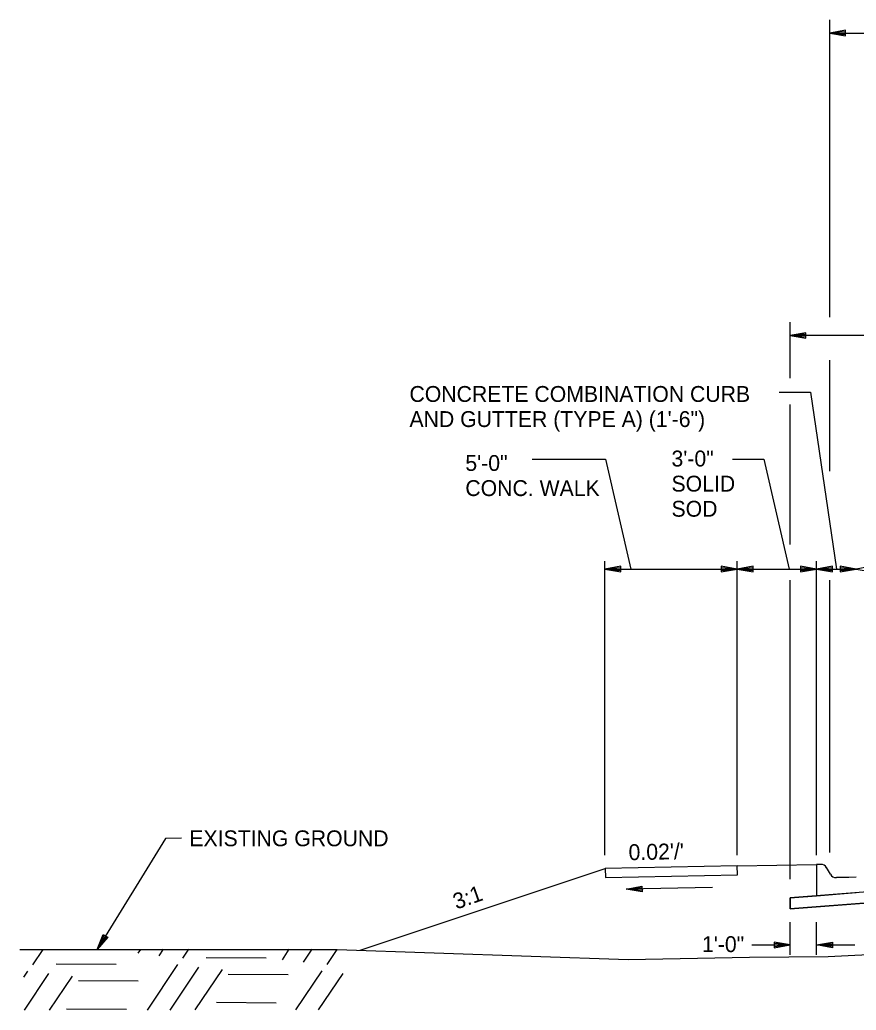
# Model space of a CAD drawing. Extents: x 1001270 to 1003428, y 1840152 to 1842912.
# Drawn here: x 1001291.53 to 1001323.16, y 1842694.01 to 1842731.46 of the extents above; entities that cross this region are included whole.
import ezdxf

# ---------------------------------------------------------------- set-up
doc = ezdxf.new("R2010")
doc.units = 0
for name, color, linetype in [('19', 7, 'Continuous'), ('20', 7, 'Continuous'), ('8', 7, 'Continuous')]:
    doc.layers.add(name, color=color, linetype=linetype)

# ---------------------------------------------------------------- blocks, each defined once
blk = doc.blocks.new('TM')
at = {"layer": '8'}
for p, q in [((-120.309, 21.181), (-119.787, -20.829)), ((0, 0), (-120.309, 21.181)), ((-31.382, 2.945), (-120.176, 10.512)), ((-119.787, -20.829), (0, 0)), ((-119.911, -10.826), (-31.307, -3.057))]:
    blk.add_line(p, q, dxfattribs=at)

msp = doc.modelspace()

# ---------------------------------------------------------------- linework, layer by layer
at = {"layer": '19'}
for p, q in [((1001322.158, 1842720.221), (1001322.158, 1842731.463)), ((1001322.758, 1842731.068), (1001322.158, 1842730.963)), ((1001322.758, 1842730.858), (1001322.758, 1842731.068)), ((1001322.158, 1842730.963), (1001360.158, 1842730.963)), ((1001322.158, 1842730.963), (1001322.758, 1842730.858)), ((1001322.758, 1842731.013), (1001322.318, 1842730.978)), ((1001322.318, 1842730.948), (1001322.758, 1842730.908)), ((1001320.658, 1842717.914), (1001320.658, 1842720.023)), ((1001321.258, 1842719.628), (1001320.658, 1842719.523)), ((1001320.658, 1842719.523), (1001321.258, 1842719.418)), ((1001361.658, 1842719.523), (1001320.658, 1842719.523)), ((1001321.258, 1842719.573), (1001320.818, 1842719.538)), ((1001320.818, 1842719.508), (1001321.258, 1842719.468)), ((1001321.258, 1842719.418), (1001321.258, 1842719.628)), ((1001322.158, 1842714.397), (1001322.158, 1842718.595)), ((1001320.248, 1842717.379), (1001321.427, 1842717.379)), ((1001321.427, 1842717.379), (1001322.415, 1842710.688)), ((1001320.658, 1842711.621), (1001320.658, 1842716.908)), ((1001310.902, 1842714.845), (1001313.681, 1842714.845)), ((1001313.681, 1842714.845), (1001314.637, 1842710.688)), ((1001318.484, 1842714.845), (1001319.663, 1842714.845)), ((1001319.663, 1842714.845), (1001320.62, 1842710.688)), ((1001313.658, 1842699.865), (1001313.658, 1842710.988)), ((1001318.658, 1842699.865), (1001318.658, 1842710.988)), ((1001321.658, 1842699.865), (1001321.658, 1842710.988)), ((1001314.258, 1842710.793), (1001313.658, 1842710.688)), ((1001313.658, 1842710.688), (1001323.158, 1842710.688)), ((1001313.658, 1842710.688), (1001314.258, 1842710.583)), ((1001314.258, 1842710.738), (1001313.818, 1842710.703)), ((1001313.818, 1842710.673), (1001314.258, 1842710.633)), ((1001314.258, 1842710.583), (1001314.258, 1842710.793)), ((1001318.058, 1842710.793), (1001318.058, 1842710.583)), ((1001318.658, 1842710.688), (1001318.058, 1842710.793)), ((1001318.498, 1842710.703), (1001318.058, 1842710.738)), ((1001318.058, 1842710.583), (1001318.658, 1842710.688)), ((1001318.058, 1842710.633), (1001318.498, 1842710.673)), ((1001319.258, 1842710.793), (1001318.658, 1842710.688)), ((1001318.658, 1842710.688), (1001319.258, 1842710.583)), ((1001319.258, 1842710.738), (1001318.818, 1842710.703)), ((1001318.818, 1842710.673), (1001319.258, 1842710.633)), ((1001319.258, 1842710.583), (1001319.258, 1842710.793)), ((1001321.058, 1842710.793), (1001321.058, 1842710.583)), ((1001321.658, 1842710.688), (1001321.058, 1842710.793)), ((1001321.498, 1842710.703), (1001321.058, 1842710.738)), ((1001321.058, 1842710.583), (1001321.658, 1842710.688)), ((1001321.058, 1842710.633), (1001321.498, 1842710.673)), ((1001322.258, 1842710.793), (1001321.658, 1842710.688)), ((1001321.658, 1842710.688), (1001322.258, 1842710.583)), ((1001322.258, 1842710.738), (1001321.818, 1842710.703)), ((1001321.818, 1842710.673), (1001322.258, 1842710.633)), ((1001322.258, 1842710.583), (1001322.258, 1842710.793)), ((1001322.558, 1842710.793), (1001322.558, 1842710.583)), ((1001323.158, 1842710.688), (1001322.558, 1842710.793)), ((1001322.998, 1842710.703), (1001322.558, 1842710.738)), ((1001322.558, 1842710.583), (1001323.158, 1842710.688)), ((1001322.558, 1842710.633), (1001322.998, 1842710.673)), ((1001323.758, 1842710.793), (1001323.158, 1842710.688)), ((1001323.158, 1842710.688), (1001323.758, 1842710.583)), ((1001320.658, 1842698.958), (1001320.658, 1842710.271)), ((1001322.158, 1842699.973), (1001322.158, 1842710.271)), ((1001304.407, 1842696.276), (1001313.661, 1842699.36)), ((1001318.66, 1842699.461), (1001313.661, 1842699.36)), ((1001313.661, 1842699.36), (1001313.674, 1842699.028)), ((1001318.66, 1842699.461), (1001321.658, 1842699.52)), ((1001318.673, 1842699.128), (1001318.66, 1842699.461)), ((1001318.66, 1842699.461), (1001318.66, 1842699.461)), ((1001321.825, 1842699.52), (1001321.658, 1842699.52)), ((1001321.658, 1842699.52), (1001321.658, 1842699.187)), ((1001322.187, 1842699.145), (1001322.041, 1842699.396)), ((1001313.674, 1842699.028), (1001318.673, 1842699.128)), ((1001321.658, 1842699.187), (1001321.658, 1842699.005)), ((1001321.658, 1842699.005), (1001321.658, 1842698.336)), ((1001322.874, 1842699.03), (1001322.408, 1842699.02)), ((1001323.158, 1842699.035), (1001322.874, 1842699.03)), ((1001322.874, 1842699.03), (1001322.874, 1842699.029)), ((1001322.874, 1842699.029), (1001322.874, 1842699.03)), ((1001321.658, 1842698.336), (1001323.158, 1842698.452)), ((1001320.658, 1842697.843), (1001320.658, 1842698.259)), ((1001320.658, 1842698.259), (1001320.658, 1842697.852)), ((1001320.658, 1842696.097), (1001320.658, 1842697.335)), ((1001321.658, 1842696.097), (1001321.658, 1842697.335)), ((1001294.458, 1842696.307), (1001294.682, 1842696.873)), ((1001294.86, 1842696.764), (1001294.458, 1842696.307)), ((1001294.532, 1842696.447), (1001294.725, 1842696.841)), ((1001294.819, 1842696.785), (1001294.555, 1842696.436)), ((1001294.682, 1842696.873), (1001294.86, 1842696.764)), ((1001320.058, 1842696.58), (1001320.058, 1842696.37)), ((1001320.658, 1842696.475), (1001320.058, 1842696.58)), ((1001320.058, 1842696.58), (1001320.058, 1842696.37)), ((1001320.658, 1842696.475), (1001320.058, 1842696.58)), ((1001321.658, 1842696.475), (1001322.258, 1842696.58)), ((1001321.658, 1842696.475), (1001322.258, 1842696.58)), ((1001322.258, 1842696.58), (1001322.258, 1842696.37)), ((1001322.258, 1842696.58), (1001322.258, 1842696.37)), ((1001292.02, 1842695.722), (1001292.411, 1842696.305)), ((1001296.005, 1842696.156), (1001296.111, 1842696.306)), ((1001296.8, 1842696.064), (1001296.966, 1842696.309)), ((1001297.695, 1842695.972), (1001297.921, 1842696.311)), ((1001301.459, 1842695.916), (1001301.721, 1842696.312)), ((1001302.254, 1842695.825), (1001302.586, 1842696.313)), ((1001303.149, 1842695.733), (1001303.53, 1842696.307)), ((1001319.209, 1842696.475), (1001320.658, 1842696.475)), ((1001319.209, 1842696.475), (1001320.658, 1842696.475)), ((1001320.498, 1842696.49), (1001320.058, 1842696.525)), ((1001320.498, 1842696.49), (1001320.058, 1842696.525)), ((1001320.058, 1842696.37), (1001320.658, 1842696.475)), ((1001320.058, 1842696.37), (1001320.658, 1842696.475)), ((1001320.058, 1842696.42), (1001320.498, 1842696.46)), ((1001320.058, 1842696.42), (1001320.498, 1842696.46)), ((1001322.258, 1842696.37), (1001321.658, 1842696.475)), ((1001321.658, 1842696.475), (1001323.107, 1842696.475)), ((1001322.258, 1842696.37), (1001321.658, 1842696.475)), ((1001321.658, 1842696.475), (1001323.107, 1842696.475)), ((1001321.818, 1842696.49), (1001322.258, 1842696.525)), ((1001321.818, 1842696.49), (1001322.258, 1842696.525)), ((1001322.258, 1842696.42), (1001321.818, 1842696.46)), ((1001322.258, 1842696.42), (1001321.818, 1842696.46)), ((1001298.583, 1842696.001), (1001300.843, 1842695.99)), ((1001291.68, 1842695.254), (1001291.834, 1842695.48)), ((1001292.908, 1842695.761), (1001295.168, 1842695.74)), ((1001296.357, 1842694.009), (1001297.509, 1842695.73)), ((1001297.212, 1842694.011), (1001298.304, 1842695.638)), ((1001298.167, 1842694.014), (1001299.199, 1842695.546)), ((1001301.967, 1842694.015), (1001302.963, 1842695.49)), ((1001291.702, 1842694.005), (1001292.629, 1842695.388)), ((1001292.657, 1842694.008), (1001293.524, 1842695.296)), ((1001293.748, 1842695.132), (1001296.008, 1842695.11)), ((1001299.413, 1842695.373), (1001301.683, 1842695.361)), ((1001302.822, 1842694.017), (1001303.758, 1842695.398)), ((1001293.295, 1842694.052), (1001295.566, 1842694.04)), ((1001298.971, 1842694.303), (1001301.23, 1842694.281))]:
    msp.add_line(p, q, dxfattribs=at)
for points in [[(1001303.53, 1842696.307), (1001314.536, 1842695.921), (1001319.13, 1842696.006), (1001322.097, 1842696.031), (1001329.443, 1842696.396), (1001339.767, 1842697.462), (1001355.933, 1842698.662), (1001361.755, 1842701.104), (1001365.939, 1842701.981), (1001371.785, 1842704.915), (1001376.097, 1842706.564), (1001383.698, 1842707.466)], [(1001361.658, 1842701.177), (1001359.158, 1842701.224), (1001320.658, 1842698.259)], [(1001320.658, 1842697.843), (1001341.158, 1842699.421), (1001359.159, 1842700.807)], [(1001320.658, 1842697.852), (1001359.159, 1842700.807), (1001361.658, 1842700.757)], [(1001297.641, 1842700.506), (1001297.041, 1842700.505), (1001294.458, 1842696.307)], [(1001320.658, 1842698.259), (1001321.658, 1842698.336)], [(1001291.53, 1842696.307), (1001303.53, 1842696.307)]]:
    msp.add_lwpolyline(points, dxfattribs=at)
for centre, start, end in [((1001321.825, 1842699.27), 30.1619, 90), ((1001322.403, 1842699.27), 210.1635, 271.1458)]:
    msp.add_arc(centre, 0.25, start, end, dxfattribs=at)
at = {"layer": '20'}
msp.add_line((1001317.728, 1842698.645), (1001314.458, 1842698.58), dxfattribs=at)

# ---------------------------------------------------------------- block references
at = {"layer": '19', "xscale": 0.0050063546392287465, "yscale": -0.0050063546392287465, "rotation": -178.8781640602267}
msp.add_blockref('TM', (1001314.458, 1842698.578), dxfattribs=at)

# ---------------------------------------------------------------- texts
at = {"layer": '19'}
for s, rotation, p in [('CONCRETE COMBINATION CURB', 360, (1001306.265, 1842717.012)), ('AND GUTTER (TYPE A) (1\'-6")', 360, (1001306.265, 1842716.062)), ('5\'-0"', 360, (1001308.378, 1842714.401)), ('3\'-0"', 360, (1001316.174, 1842714.57)), ('SOLID ', 360, (1001316.174, 1842713.62)), ('CONC. WALK', 360, (1001308.378, 1842713.451)), ('SOD', 360, (1001316.174, 1842712.67)), ("0.02'/'", 1.1496, (1001314.556, 1842699.678)), ('3:1', 19.5057, (1001308.038, 1842697.807))]:
    msp.add_text(s, height=0.6, rotation=rotation, dxfattribs=at).set_placement(p)
for s, p in [('EXISTING GROUND', (1001297.941, 1842700.206)), ('1\'-0"', (1001317.326, 1842696.203))]:
    msp.add_text(s, height=0.6, dxfattribs=at).set_placement(p)

doc.saveas('drawing.dxf')
